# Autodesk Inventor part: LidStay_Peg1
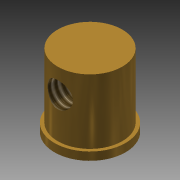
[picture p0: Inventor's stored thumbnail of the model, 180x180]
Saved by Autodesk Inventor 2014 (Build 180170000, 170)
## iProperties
Created: 2014-03
Part Number: LidStay_Peg1
Material: Brass, Soft Yellow
Document SubType Name: Modeling
Designer: Beast
Density: 8.47 g/cm^3
Appearance: Brass - Satin
Author: Beast
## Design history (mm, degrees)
sketch "Sketch1"
  geometry: C1 r 6.985 at (0, 0); 1 further point
  constraints: 1 centre point, 1 coincident
  dimensions: "d0" = 13.97 diameter of C1
extrude "Extrusion1" new body sketch "Sketch1" distance "d1" = 1.5875; taper "d2" = 0 deg
sketch "Sketch2"
  geometry: C1 r 6.985 at (0, 0) reference; C2 r 6.35 at (0, 0)
  constraints: 1 centre point, 1 coincident
  dimensions: "d3" = 12.7 diameter of C2
extrude "Extrusion2" join sketch "Sketch2" distance "d4" = 12.7; taper "d5" = 0 deg
workplane "Work Plane1"
sketch "Sketch3"
  geometry: L1 (-6.985, -1.587)-(6.985, -1.587) reference; 2 further points
  dimensions: "d6" = 9.525 distance from line of L1 point (0, 7.938)
hole "Hole1" sketch "Sketch3" at (0, 7.938) diameter "d7" = 4.9784; stored, may be unused: countersink angle "d11" = 82 deg, drill point angle "d13" = 118 deg; dims "d8" = 19.05, "d9" = 9.525, "d10" = 6.35, "d12" = 25.4
body "Solid1"
